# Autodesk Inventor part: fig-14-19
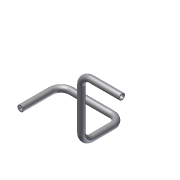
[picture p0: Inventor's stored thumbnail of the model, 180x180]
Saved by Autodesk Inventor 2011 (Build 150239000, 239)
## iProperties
Created: 2005-03
Part Number: fig-14-19
Document SubType Name: Modeling
Designer: CADCIM
Manufacturer: Standard
Standards Organization: Custom
Density: 1 g/cm^3
Author: CADCIM
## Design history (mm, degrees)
sketch "Sketch1"
  geometry: L1 (-32.875, 0)-(-32.875, 40); L2 (-32.875, 40)-(27.125, 40); L3 (27.125, 40)-(27.125, 0); 1 further point
  constraints: 6 end point, 1 horizontal alignment, 1 parallel, 1 perpendicular, 1 vertical, 1 other
  dimensions: "d0" = 40 distance of L1.start L1.end; "d1" = 60 distance of L1.end L2.end; "d2" = 40 distance of L2.end L3.end
workplane "Work Plane1"
sketch "Sketch2"
  geometry: L1 (0, 0)-(0, 60); L2 (0, 60)-(40, 60)
  constraints: 4 end point, 1 perpendicular, 1 vertical
  dimensions: "d3" = 60 distance of L1.start L1.end; "d4" = 40 distance of L1.end L2.end
sketch "3D Sketch1" dims "d5" = 10, "d6" = 10 (= d5)
  geometry: L1 through (10, 10) direction (-1, -2.22e-16); L2 through (0, 50) direction (-2.22e-16, 1); 18 other entities
  constraints: 2 horizontal, 2 vertical
  dimensions: "d7" = 10 distance of the line from the sketch origin of L1 (= d5); "d8" = 10 dimension on L2 (= d5)
workplane "Work Plane2"
sketch "Sketch3"
  geometry: C1 r 3 at (0, 0); C2 r 2 at (0, 0)
  constraints: 2 centre point, 1 coincident
  dimensions: "d9" = 6 diameter of C1; "d10" = 4 diameter of C2
sweep "Sweep1" sketch "Sketch3" dims "d11" = 0
body "Solid1"
